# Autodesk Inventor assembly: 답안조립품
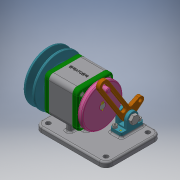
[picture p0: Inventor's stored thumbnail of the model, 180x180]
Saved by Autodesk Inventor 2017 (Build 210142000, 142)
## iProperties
Part Number: 답안조립품
Material: 일반
Document SubType Name: Assembly
Designer: 00-00
Author: 00-00
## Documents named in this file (19)
- C:\Users\00-00\Desktop\601106V1037\답안조립품.iam
- C:\Users\00-00\Desktop\601106V1037\본체.ipt
- C:\Users\00-00\Desktop\601106V1037\V-벨트풀리.ipt
- C:\Users\00-00\Desktop\601106V1037\너트 M8.ipt
- C:\Users\00-00\Desktop\601106V1037\너트 M10x1.ipt
- C:\Users\00-00\Desktop\601106V1037\돌림판.ipt
- C:\Users\00-00\Desktop\601106V1037\멈춤나사 M3x5.ipt
- C:\Users\00-00\Desktop\601106V1037\베어링 6004.ipt
- C:\Users\00-00\Desktop\601106V1037\볼트 M4.ipt
- C:\Users\00-00\Desktop\601106V1037\오일 실 17 30 5.ipt
- C:\Users\00-00\Desktop\601106V1037\와셔 8x15.5.ipt
- C:\Users\00-00\Desktop\601106V1037\축.ipt
- C:\Users\00-00\Desktop\601106V1037\커버.ipt
- C:\Users\00-00\Desktop\601106V1037\크랭크.ipt
- C:\Users\00-00\Desktop\601106V1037\키 4 x 4 x 8.ipt
- C:\Users\00-00\Desktop\601106V1037\키 5 x 5 x 12.ipt
- C:\Users\00-00\Desktop\601106V1037\핀 3 x 8.ipt
- C:\Users\00-00\Desktop\601106V1037\힌지 축.ipt
- C:\Users\00-00\Desktop\601106V1037\힌지.ipt
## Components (3 placed, 2 different names)
1. V-벨트풀리:1
2. 핀 3 x 8:1 — 플러쉬:3
3. 핀 3 x 8:2 — 플러쉬:4
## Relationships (2: Flush 2)
- 플러쉬:3 [Flush]: 핀 3 x 8:1
- 플러쉬:4 [Flush]: 핀 3 x 8:2
